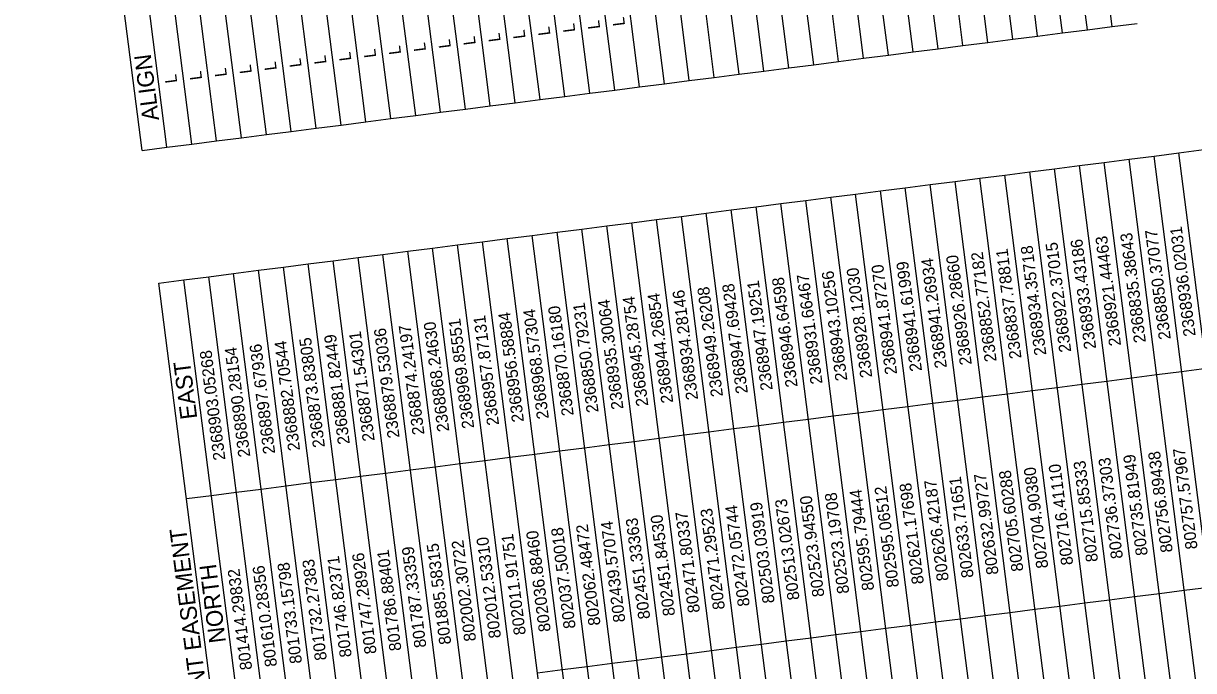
# Model space of a CAD drawing. Extents: x 2364621 to 2374814, y 792603 to 806745.
# Drawn here: x 2365969 to 2368280, y 801956 to 803235 of the extents above; entities that cross this region are included whole.
import ezdxf

# ---------------------------------------------------------------- set-up
doc = ezdxf.new("R2010")
doc.units = 0
for name, color, linetype in [('CTL Sheet Notes CELL', 7, 'Continuous'), ('CTL Sheet Table Cell', 7, 'Continuous'), ('CTL Sheet Text', 7, 'Continuous')]:
    doc.layers.add(name, color=color, linetype=linetype)

msp = doc.modelspace()

# ---------------------------------------------------------------- linework, layer by layer
at = {"layer": 'CTL Sheet Table Cell'}
for p, q in [((2368070.1, 803222.1), (2367835.9, 805055.9)), ((2368119.3, 803228.4), (2367885.1, 805062.2)), ((2367922.8, 803203.3), (2367688.6, 805037.1)), ((2367971.9, 803209.6), (2367737.7, 805043.3)), ((2368021, 803215.9), (2367786.8, 805049.6)), ((2367726.3, 803178.2), (2367492.1, 805012)), ((2367775.4, 803184.5), (2367541.2, 805018.2)), ((2367824.5, 803190.8), (2367590.3, 805024.5)), ((2367873.7, 803197), (2367639.5, 805030.8)), ((2367529.8, 803153.1), (2367295.6, 804986.9)), ((2367579, 803159.4), (2367344.8, 804993.1)), ((2367628.1, 803165.7), (2367393.9, 804999.4)), ((2367677.2, 803172), (2367443, 805005.7)), ((2367382.5, 803134.3), (2367148.3, 804968.1)), ((2367431.6, 803140.6), (2367197.4, 804974.3)), ((2367480.7, 803146.9), (2367246.5, 804980.6)), ((2367186, 803109.2), (2366951.8, 804943)), ((2367235.1, 803115.5), (2367000.9, 804949.2)), ((2367284.2, 803121.8), (2367050, 804955.5)), ((2367333.4, 803128), (2367099.2, 804961.8)), ((2366989.5, 803084.1), (2366755.3, 804917.9)), ((2367038.7, 803090.4), (2366804.5, 804924.1)), ((2367087.8, 803096.7), (2366853.6, 804930.4)), ((2367136.9, 803102.9), (2366902.7, 804936.7)), ((2366842.2, 803065.3), (2366608, 804899)), ((2366891.3, 803071.6), (2366657.1, 804905.3)), ((2366940.4, 803077.9), (2366706.2, 804911.6)), ((2366645.7, 803040.2), (2366411.5, 804874)), ((2366694.8, 803046.5), (2366460.6, 804880.2)), ((2366744, 803052.8), (2366509.7, 804886.5)), ((2366793.1, 803059), (2366558.9, 804892.8)), ((2366449.2, 803015.1), (2366215, 804848.9)), ((2366498.4, 803021.4), (2366264.2, 804855.1)), ((2366547.5, 803027.7), (2366313.3, 804861.4)), ((2366596.6, 803033.9), (2366362.4, 804867.7)), ((2366301.9, 802996.3), (2366067.7, 804830)), ((2366351, 803002.6), (2366116.8, 804836.3)), ((2366400.1, 803008.8), (2366165.9, 804842.6)), ((2366203.7, 802983.8), (2365969.5, 804817.5)), ((2366252.8, 802990), (2366018.6, 804823.8)), ((2368119.3, 803228.4), (2368168.4, 803234.7)), ((2367922.8, 803203.3), (2367971.9, 803209.6)), ((2367971.9, 803209.6), (2368021, 803215.9)), ((2368021, 803215.9), (2368070.1, 803222.1)), ((2368070.1, 803222.1), (2368119.3, 803228.4)), ((2367726.3, 803178.2), (2367775.4, 803184.5)), ((2367775.4, 803184.5), (2367824.5, 803190.8)), ((2367824.5, 803190.8), (2367873.7, 803197)), ((2367873.7, 803197), (2367922.8, 803203.3)), ((2367579, 803159.4), (2367628.1, 803165.7)), ((2367628.1, 803165.7), (2367677.2, 803172)), ((2367677.2, 803172), (2367726.3, 803178.2)), ((2367382.5, 803134.3), (2367431.6, 803140.6)), ((2367431.6, 803140.6), (2367480.7, 803146.9)), ((2367480.7, 803146.9), (2367529.8, 803153.1)), ((2367529.8, 803153.1), (2367579, 803159.4)), ((2367186, 803109.2), (2367235.1, 803115.5)), ((2367235.1, 803115.5), (2367284.2, 803121.8)), ((2367284.2, 803121.8), (2367333.4, 803128)), ((2367333.4, 803128), (2367382.5, 803134.3)), ((2367038.7, 803090.4), (2367087.8, 803096.7)), ((2367087.8, 803096.7), (2367136.9, 803102.9)), ((2367136.9, 803102.9), (2367186, 803109.2)), ((2366842.2, 803065.3), (2366891.3, 803071.6)), ((2366891.3, 803071.6), (2366940.4, 803077.9)), ((2366940.4, 803077.9), (2366989.5, 803084.1)), ((2366989.5, 803084.1), (2367038.7, 803090.4)), ((2366645.7, 803040.2), (2366694.8, 803046.5)), ((2366694.8, 803046.5), (2366744, 803052.8)), ((2366744, 803052.8), (2366793.1, 803059)), ((2366793.1, 803059), (2366842.2, 803065.3)), ((2366498.4, 803021.4), (2366547.5, 803027.7)), ((2366547.5, 803027.7), (2366596.6, 803033.9)), ((2366596.6, 803033.9), (2366645.7, 803040.2)), ((2366301.9, 802996.3), (2366351, 803002.6)), ((2366351, 803002.6), (2366400.1, 803008.8)), ((2366400.1, 803008.8), (2366449.2, 803015.1)), ((2366449.2, 803015.1), (2366498.4, 803021.4)), ((2366203.7, 802983.8), (2366252.8, 802990)), ((2366252.8, 802990), (2366301.9, 802996.3)), ((2368201.8, 802972.7), (2368250.9, 802979)), ((2368250.9, 802979), (2368300.1, 802985.3)), ((2368485.1, 801145.3), (2368250.9, 802979)), ((2368005.4, 802947.6), (2368054.5, 802953.9)), ((2368054.5, 802953.9), (2368103.6, 802960.2)), ((2368288.7, 801120.2), (2368054.5, 802953.9)), ((2368103.6, 802960.2), (2368152.7, 802966.5)), ((2368337.8, 801126.4), (2368103.6, 802960.2)), ((2368152.7, 802966.5), (2368201.8, 802972.7)), ((2368386.9, 801132.7), (2368152.7, 802966.5)), ((2368436, 801139), (2368201.8, 802972.7)), ((2367858, 802928.8), (2367907.1, 802935.1)), ((2367907.1, 802935.1), (2367956.2, 802941.4)), ((2368141.3, 801101.4), (2367907.1, 802935.1)), ((2367956.2, 802941.4), (2368005.4, 802947.6)), ((2368190.4, 801107.6), (2367956.2, 802941.4)), ((2368239.6, 801113.9), (2368005.4, 802947.6)), ((2367661.5, 802903.7), (2367710.6, 802910)), ((2367710.6, 802910), (2367759.8, 802916.3)), ((2367944.9, 801076.3), (2367710.6, 802910)), ((2367759.8, 802916.3), (2367808.9, 802922.5)), ((2367994, 801082.5), (2367759.8, 802916.3)), ((2367808.9, 802922.5), (2367858, 802928.8)), ((2368043.1, 801088.8), (2367808.9, 802922.5)), ((2368092.2, 801095.1), (2367858, 802928.8)), ((2367465.1, 802878.6), (2367514.2, 802884.9)), ((2367514.2, 802884.9), (2367563.3, 802891.2)), ((2367748.4, 801051.2), (2367514.2, 802884.9)), ((2367563.3, 802891.2), (2367612.4, 802897.4)), ((2367797.5, 801057.4), (2367563.3, 802891.2)), ((2367612.4, 802897.4), (2367661.5, 802903.7)), ((2367846.6, 801063.7), (2367612.4, 802897.4)), ((2367895.7, 801070), (2367661.5, 802903.7)), ((2367317.7, 802859.8), (2367366.8, 802866.1)), ((2367366.8, 802866.1), (2367415.9, 802872.4)), ((2367601, 801032.3), (2367366.8, 802866.1)), ((2367415.9, 802872.4), (2367465.1, 802878.6)), ((2367650.1, 801038.6), (2367415.9, 802872.4)), ((2367699.3, 801044.9), (2367465.1, 802878.6)), ((2367121.2, 802834.7), (2367170.4, 802841)), ((2367170.4, 802841), (2367219.5, 802847.3)), ((2367404.6, 801007.3), (2367170.4, 802841)), ((2367219.5, 802847.3), (2367268.6, 802853.5)), ((2367453.7, 801013.5), (2367219.5, 802847.3)), ((2367268.6, 802853.5), (2367317.7, 802859.8)), ((2367502.8, 801019.8), (2367268.6, 802853.5)), ((2367551.9, 801026.1), (2367317.7, 802859.8)), ((2366924.8, 802809.6), (2366973.9, 802815.9)), ((2366973.9, 802815.9), (2367023, 802822.2)), ((2367208.1, 800982.2), (2366973.9, 802815.9)), ((2367023, 802822.2), (2367072.1, 802828.4)), ((2367257.2, 800988.4), (2367023, 802822.2)), ((2367072.1, 802828.4), (2367121.2, 802834.7)), ((2367306.3, 800994.7), (2367072.1, 802828.4)), ((2367355.4, 801001), (2367121.2, 802834.7)), ((2366728.3, 802784.5), (2366777.4, 802790.8)), ((2366777.4, 802790.8), (2366826.5, 802797.1)), ((2367011.6, 800957.1), (2366777.4, 802790.8)), ((2366826.5, 802797.1), (2366875.6, 802803.3)), ((2367060.7, 800963.3), (2366826.5, 802797.1)), ((2366875.6, 802803.3), (2366924.8, 802809.6)), ((2367109.8, 800969.6), (2366875.6, 802803.3)), ((2367159, 800975.9), (2366924.8, 802809.6)), ((2366580.9, 802765.7), (2366630.1, 802772)), ((2366630.1, 802772), (2366679.2, 802778.3)), ((2366864.3, 800938.2), (2366630.1, 802772)), ((2366679.2, 802778.3), (2366728.3, 802784.5)), ((2366913.4, 800944.5), (2366679.2, 802778.3)), ((2366962.5, 800950.8), (2366728.3, 802784.5)), ((2366384.5, 802740.6), (2366433.6, 802746.9)), ((2366433.6, 802746.9), (2366482.7, 802753.2)), ((2366667.8, 800913.2), (2366433.6, 802746.9)), ((2366482.7, 802753.2), (2366531.8, 802759.4)), ((2366716.9, 800919.4), (2366482.7, 802753.2)), ((2366531.8, 802759.4), (2366580.9, 802765.7)), ((2366766, 800925.7), (2366531.8, 802759.4)), ((2366815.1, 800932), (2366580.9, 802765.7)), ((2366237.1, 802721.8), (2366286.2, 802728.1)), ((2366471.3, 800888.1), (2366237.1, 802721.8)), ((2366286.2, 802728.1), (2366335.3, 802734.3)), ((2366520.4, 800894.3), (2366286.2, 802728.1)), ((2366335.3, 802734.3), (2366384.5, 802740.6)), ((2366569.6, 800900.6), (2366335.3, 802734.3)), ((2366618.7, 800906.9), (2366384.5, 802740.6)), ((2368158, 802534.5), (2368207.1, 802540.8)), ((2368207.1, 802540.8), (2368256.2, 802547)), ((2368256.2, 802547), (2368305.3, 802553.3)), ((2367961.5, 802509.4), (2368010.6, 802515.7)), ((2368010.6, 802515.7), (2368059.7, 802521.9)), ((2368059.7, 802521.9), (2368108.8, 802528.2)), ((2368108.8, 802528.2), (2368158, 802534.5)), ((2367765, 802484.3), (2367814.1, 802490.6)), ((2367814.1, 802490.6), (2367863.3, 802496.9)), ((2367863.3, 802496.9), (2367912.4, 802503.1)), ((2367912.4, 802503.1), (2367961.5, 802509.4)), ((2367617.7, 802465.5), (2367666.8, 802471.8)), ((2367666.8, 802471.8), (2367715.9, 802478)), ((2367715.9, 802478), (2367765, 802484.3)), ((2367421.2, 802440.4), (2367470.3, 802446.7)), ((2367470.3, 802446.7), (2367519.4, 802452.9)), ((2367519.4, 802452.9), (2367568.5, 802459.2)), ((2367568.5, 802459.2), (2367617.7, 802465.5)), ((2367224.7, 802415.3), (2367273.8, 802421.6)), ((2367273.8, 802421.6), (2367323, 802427.8)), ((2367323, 802427.8), (2367372.1, 802434.1)), ((2367372.1, 802434.1), (2367421.2, 802440.4)), ((2367077.4, 802396.5), (2367126.5, 802402.8)), ((2367126.5, 802402.8), (2367175.6, 802409)), ((2367175.6, 802409), (2367224.7, 802415.3)), ((2366880.9, 802371.4), (2366930, 802377.7)), ((2366930, 802377.7), (2366979.1, 802383.9)), ((2366979.1, 802383.9), (2367028.2, 802390.2)), ((2367028.2, 802390.2), (2367077.4, 802396.5)), ((2366684.4, 802346.3), (2366733.5, 802352.6)), ((2366733.5, 802352.6), (2366782.7, 802358.8)), ((2366782.7, 802358.8), (2366831.8, 802365.1)), ((2366831.8, 802365.1), (2366880.9, 802371.4)), ((2366537.1, 802327.5), (2366586.2, 802333.7)), ((2366586.2, 802333.7), (2366635.3, 802340)), ((2366635.3, 802340), (2366684.4, 802346.3)), ((2366340.6, 802302.4), (2366389.7, 802308.7)), ((2366389.7, 802308.7), (2366438.8, 802314.9)), ((2366438.8, 802314.9), (2366488, 802321.2)), ((2366488, 802321.2), (2366537.1, 802327.5)), ((2366291.5, 802296.1), (2366340.6, 802302.4)), ((2368261.4, 802115.1), (2368310.6, 802121.3)), ((2368114.1, 802096.3), (2368163.2, 802102.5)), ((2368163.2, 802102.5), (2368212.3, 802108.8)), ((2368212.3, 802108.8), (2368261.4, 802115.1)), ((2367917.6, 802071.2), (2367966.7, 802077.4)), ((2367966.7, 802077.4), (2368015.9, 802083.7)), ((2368015.9, 802083.7), (2368065, 802090)), ((2368065, 802090), (2368114.1, 802096.3)), ((2367721.2, 802046.1), (2367770.3, 802052.3)), ((2367770.3, 802052.3), (2367819.4, 802058.6)), ((2367819.4, 802058.6), (2367868.5, 802064.9)), ((2367868.5, 802064.9), (2367917.6, 802071.2)), ((2367573.8, 802027.2), (2367622.9, 802033.5)), ((2367622.9, 802033.5), (2367672, 802039.8)), ((2367672, 802039.8), (2367721.2, 802046.1)), ((2367377.3, 802002.2), (2367426.4, 802008.4)), ((2367426.4, 802008.4), (2367475.6, 802014.7)), ((2367475.6, 802014.7), (2367524.7, 802021)), ((2367524.7, 802021), (2367573.8, 802027.2)), ((2367180.9, 801977.1), (2367230, 801983.3)), ((2367230, 801983.3), (2367279.1, 801989.6)), ((2367279.1, 801989.6), (2367328.2, 801995.9)), ((2367328.2, 801995.9), (2367377.3, 802002.2)), ((2367033.5, 801958.2), (2367082.6, 801964.5)), ((2367082.6, 801964.5), (2367131.7, 801970.8)), ((2367131.7, 801970.8), (2367180.9, 801977.1)), ((2366984.4, 801952), (2367033.5, 801958.2))]:
    msp.add_line(p, q, dxfattribs=at)

# ---------------------------------------------------------------- texts
at = {"layer": 'CTL Sheet Notes CELL'}
for s, height, p in [('ALIGN', 33.01, (2366237.5, 803044.2)), ('EAST', 33.01, (2366312.8, 802454.6)), ('ROW ROW MARKER PERMANENT EASEMENT', 33.011, (2366413.8, 801273.3)), ('NORTH', 33.01, (2366369.3, 802012.7))]:
    msp.add_text(s, height=height, rotation=97.2784, dxfattribs=at).set_placement(p)
at = {"layer": 'CTL Sheet Text'}
for s, height, p in [('L', 23.6, (2367059.2, 803218.3)), ('L', 23.6, (2367108.3, 803224.6)), ('L', 23.6, (2367157.4, 803230.8)), ('L', 23.6, (2366862.7, 803193.2)), ('L', 23.6, (2366911.8, 803199.5)), ('L', 23.6, (2366960.9, 803205.7)), ('L', 23.6, (2367010.1, 803212)), ('L', 23.6, (2366666.2, 803168.1)), ('L', 23.6, (2366715.3, 803174.4)), ('L', 23.6, (2366764.5, 803180.6)), ('L', 23.6, (2366813.6, 803186.9)), ('L', 23.6, (2366518.9, 803149.3)), ('L', 23.6, (2366568, 803155.5)), ('L', 23.6, (2366617.1, 803161.8)), ('L', 23.6, (2366322.4, 803124.2)), ('L', 23.6, (2366371.5, 803130.5)), ('L', 23.6, (2366420.6, 803136.7)), ('L', 23.6, (2366469.8, 803143)), ('L', 23.6, (2366273.3, 803117.9)), ('2368921.44463', 23.579, (2368136.7, 802598.7)), ('2368835.38643', 23.579, (2368185.8, 802605)), ('2368850.37077', 23.579, (2368234.9, 802611.3)), ('2368936.02031', 23.579, (2368284, 802617.5)), ('2368934.35718', 23.579, (2367989.3, 802579.9)), ('2368922.37015', 23.579, (2368038.4, 802586.2)), ('2368933.43186', 23.579, (2368087.6, 802592.5)), ('2368941.26934', 23.579, (2367792.9, 802554.8)), ('2368926.28660', 23.579, (2367842, 802561.1)), ('2368852.77182', 23.579, (2367891.1, 802567.4)), ('2368837.78811', 23.579, (2367940.2, 802573.6)), ('2368943.10256', 23.579, (2367596.4, 802529.7)), ('2368928.12030', 23.579, (2367645.5, 802536)), ('2368941.87270', 23.579, (2367694.6, 802542.3)), ('2368941.61999', 23.579, (2367743.7, 802548.5)), ('2368947.19251', 23.579, (2367449, 802510.9)), ('2368946.64598', 23.579, (2367498.2, 802517.2)), ('2368931.66467', 23.579, (2367547.3, 802523.4)), ('2368944.26854', 23.579, (2367252.6, 802485.8)), ('2368934.28146', 23.579, (2367301.7, 802492.1)), ('2368949.26208', 23.579, (2367350.8, 802498.4)), ('2368947.69428', 23.579, (2367399.9, 802504.6)), ('2368870.16180', 23.579, (2367056.1, 802460.7)), ('2368850.79231', 23.579, (2367105.2, 802467)), ('2368935.30064', 23.579, (2367154.3, 802473.3)), ('2368945.28754', 23.579, (2367203.4, 802479.5)), ('2368957.87131', 23.579, (2366908.7, 802441.9)), ('2368956.58884', 23.579, (2366957.9, 802448.2)), ('2368968.57304', 23.579, (2367007, 802454.4)), ('2368879.53036', 23.579, (2366712.3, 802416.8)), ('2368874.24197', 23.579, (2366761.4, 802423.1)), ('2368868.24630', 23.579, (2366810.5, 802429.3)), ('2368969.85551', 23.579, (2366859.6, 802435.6)), ('2368882.70544', 23.579, (2366515.8, 802391.7)), ('2368873.83805', 23.579, (2366564.9, 802398)), ('2368881.82449', 23.579, (2366614, 802404.3)), ('2368871.54301', 23.579, (2366663.1, 802410.5)), ('2368903.05268', 23.579, (2366368.4, 802372.9)), ('2368890.28154', 23.579, (2366417.6, 802379.2)), ('2368897.67936', 23.579, (2366466.7, 802385.4)), ('802736.37303', 23.579, (2368140.5, 802178.4)), ('802735.81949', 23.579, (2368189.6, 802184.6)), ('802756.89438', 23.579, (2368238.7, 802190.9)), ('802757.57967', 23.579, (2368287.8, 802197.2)), ('802704.90380', 23.579, (2367993.1, 802159.5)), ('802716.41110', 23.579, (2368042.2, 802165.8)), ('802715.85333', 23.579, (2368091.3, 802172.1)), ('802626.42187', 23.579, (2367796.6, 802134.5)), ('802633.71651', 23.579, (2367845.7, 802140.7)), ('802632.99727', 23.579, (2367894.9, 802147)), ('802705.60288', 23.579, (2367944, 802153.3)), ('802523.19708', 23.579, (2367600.2, 802109.4)), ('802595.79444', 23.579, (2367649.3, 802115.6)), ('802595.06512', 23.579, (2367698.4, 802121.9)), ('802621.17698', 23.579, (2367747.5, 802128.2)), ('802472.05744', 23.579, (2367403.7, 802084.3)), ('802503.03919', 23.579, (2367452.8, 802090.5)), ('802513.02673', 23.579, (2367501.9, 802096.8)), ('802523.94550', 23.579, (2367551, 802103.1)), ('802451.84530', 23.579, (2367256.3, 802065.4)), ('802471.80337', 23.579, (2367305.4, 802071.7)), ('802471.29523', 23.579, (2367354.6, 802078)), ('802037.50018', 23.579, (2367059.9, 802040.4)), ('802062.48472', 23.579, (2367109, 802046.6)), ('802439.57074', 23.579, (2367158.1, 802052.9)), ('802451.33363', 23.579, (2367207.2, 802059.2)), ('802002.30722', 23.579, (2366863.4, 802015.3)), ('802012.53310', 23.579, (2366912.5, 802021.5)), ('802011.91751', 23.579, (2366961.6, 802027.8)), ('802036.88460', 23.579, (2367010.7, 802034.1)), ('801786.88401', 23.579, (2366716, 801996.4)), ('801787.33359', 23.579, (2366765.2, 802002.7)), ('801885.58315', 23.579, (2366814.3, 802009)), ('801733.15798', 23.579, (2366519.6, 801971.3)), ('801732.27383', 23.579, (2366568.7, 801977.6)), ('801746.82371', 23.579, (2366617.8, 801983.9)), ('801747.28926', 23.579, (2366666.9, 801990.2)), ('801414.29832', 23.579, (2366421.3, 801958.8)), ('801610.28356', 23.579, (2366470.4, 801965.1))]:
    msp.add_text(s, height=height, rotation=97.2784, dxfattribs=at).set_placement(p)

doc.saveas('drawing.dxf')
